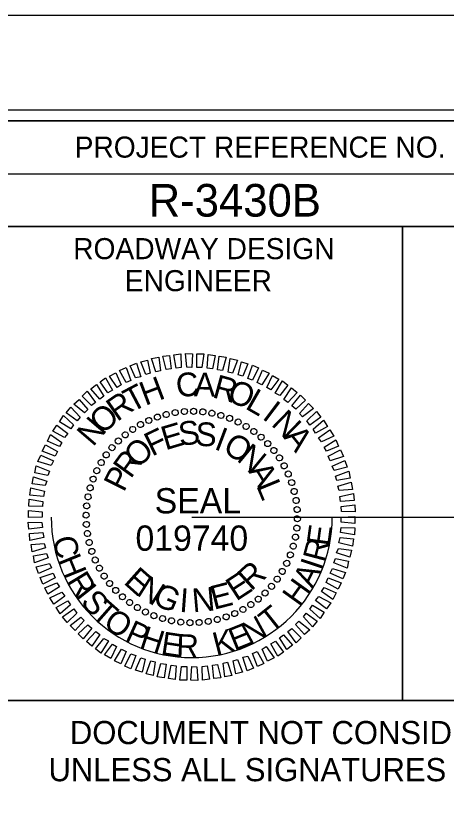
# Model space of a CAD drawing. Extents: x 1263639 to 1265460, y 747271 to 748371.
# Drawn here: x 1265113.9 to 1265216.1, y 748185.2 to 748370.7 of the extents above; entities that cross this region are included whole.
import ezdxf

# ---------------------------------------------------------------- set-up
doc = ezdxf.new("R2010")
doc.units = 0
for name, color, linetype in [('Prop Drainage Structure Bridge', 7, 'Continuous'), ('Prop Drainage Structure Bridge Opening', 7, 'Continuous'), ('Prop Grid Mask', 7, 'Continuous'), ('Prop Horizontal Alignment', 7, 'Continuous'), ('Prop Paved Shoulder', 7, 'Continuous'), ('Prop Terminator CELL', 7, 'Continuous'), ('Prop VPI Label', 7, 'Continuous'), ('Sheet Border Standard 30in CELL', 7, 'Continuous'), ('Sheet Layout Plan Border', 7, 'Continuous')]:
    doc.layers.add(name, color=color, linetype=linetype)

msp = doc.modelspace()

# ---------------------------------------------------------------- linework, layer by layer
at = {"layer": 'Prop Drainage Structure Bridge'}
for p, q in [((1265151.8, 748276.5), (1265151.8, 748276.5)), ((1265153.95, 748276.8), (1265153.95, 748276.8)), ((1265156.15, 748276.85), (1265156.15, 748276.85)), ((1265158.35, 748276.7), (1265158.35, 748276.7)), ((1265160.5, 748276.35), (1265160.5, 748276.35)), ((1265145.5, 748274.7), (1265145.5, 748274.7)), ((1265147.5, 748275.5), (1265147.5, 748275.5)), ((1265149.6, 748276.1), (1265149.6, 748276.1)), ((1265162.6, 748275.9), (1265162.6, 748275.9)), ((1265164.7, 748275.2), (1265164.7, 748275.2)), ((1265166.7, 748274.3), (1265166.7, 748274.3)), ((1265141.65, 748272.55), (1265141.65, 748272.55)), ((1265143.55, 748273.7), (1265143.55, 748273.7)), ((1265168.65, 748273.3), (1265168.65, 748273.3)), ((1265139.9, 748271.3), (1265139.9, 748271.3)), ((1265170.45, 748272.05), (1265170.45, 748272.05)), ((1265172.2, 748270.7), (1265172.2, 748270.7)), ((1265138.25, 748269.8), (1265138.25, 748269.8)), ((1265173.75, 748269.2), (1265173.75, 748269.2)), ((1265136.75, 748268.25), (1265136.75, 748268.25)), ((1265175.25, 748267.55), (1265175.25, 748267.55)), ((1265135.4, 748266.5), (1265135.4, 748266.5)), ((1265176.5, 748265.8), (1265176.5, 748265.8)), ((1265134.15, 748264.7), (1265134.15, 748264.7)), ((1265177.65, 748263.9), (1265177.65, 748263.9)), ((1265133.15, 748262.75), (1265133.15, 748262.75)), ((1265178.65, 748261.95), (1265178.65, 748261.95)), ((1265132.25, 748260.75), (1265132.25, 748260.75)), ((1265179.45, 748259.95), (1265179.45, 748259.95)), ((1265131.55, 748258.65), (1265131.55, 748258.65)), ((1265180.05, 748257.85), (1265180.05, 748257.85)), ((1265131.1, 748256.55), (1265131.1, 748256.55)), ((1265130.75, 748254.4), (1265130.75, 748254.4)), ((1265180.45, 748255.65), (1265180.45, 748255.65)), ((1265130.6, 748252.2), (1265130.6, 748252.2)), ((1265180.75, 748253.5), (1265180.75, 748253.5)), ((1265155.7, 748251.75), (1265155.7, 748251.75)), ((1265180.8, 748251.3), (1265180.8, 748251.3)), ((1265130.65, 748250), (1265130.65, 748250)), ((1265180.65, 748249.1), (1265180.65, 748249.1)), ((1265130.95, 748247.85), (1265130.95, 748247.85)), ((1265180.3, 748246.95), (1265180.3, 748246.95)), ((1265131.35, 748245.65), (1265131.35, 748245.65)), ((1265179.85, 748244.85), (1265179.85, 748244.85)), ((1265131.95, 748243.55), (1265131.95, 748243.55)), ((1265179.15, 748242.75), (1265179.15, 748242.75)), ((1265132.75, 748241.55), (1265132.75, 748241.55)), ((1265133.75, 748239.6), (1265133.75, 748239.6)), ((1265178.25, 748240.75), (1265178.25, 748240.75)), ((1265134.9, 748237.7), (1265134.9, 748237.7)), ((1265177.25, 748238.8), (1265177.25, 748238.8)), ((1265136.15, 748235.95), (1265136.15, 748235.95)), ((1265176, 748237), (1265176, 748237)), ((1265137.65, 748234.3), (1265137.65, 748234.3)), ((1265173.15, 748233.7), (1265173.15, 748233.7)), ((1265174.65, 748235.25), (1265174.65, 748235.25)), ((1265139.2, 748232.8), (1265139.2, 748232.8)), ((1265171.5, 748232.2), (1265171.5, 748232.2)), ((1265140.95, 748231.45), (1265140.95, 748231.45)), ((1265142.75, 748230.2), (1265142.75, 748230.2)), ((1265167.85, 748229.8), (1265167.85, 748229.8)), ((1265169.75, 748230.95), (1265169.75, 748230.95)), ((1265144.7, 748229.2), (1265144.7, 748229.2)), ((1265146.7, 748228.3), (1265146.7, 748228.3)), ((1265163.9, 748228), (1265163.9, 748228)), ((1265165.9, 748228.8), (1265165.9, 748228.8)), ((1265148.8, 748227.6), (1265148.8, 748227.6)), ((1265150.9, 748227.15), (1265150.9, 748227.15)), ((1265153.05, 748226.8), (1265153.05, 748226.8)), ((1265155.25, 748226.65), (1265155.25, 748226.65)), ((1265157.45, 748226.7), (1265157.45, 748226.7)), ((1265159.6, 748227), (1265159.6, 748227)), ((1265161.8, 748227.4), (1265161.8, 748227.4))]:
    msp.add_line(p, q, dxfattribs=at)
for points in [[(1265147.2, 748286.2), (1265146.15, 748289.35), (1265147.85, 748289.7), (1265148.25, 748286.45)], [(1265149.6, 748286.75), (1265148.8, 748289.95), (1265150.45, 748290.1), (1265150.8, 748286.9)], [(1265152, 748287.05), (1265151.45, 748290.25), (1265153.15, 748290.45), (1265153.2, 748287.2)], [(1265154.5, 748287.3), (1265154.25, 748290.55), (1265155.9, 748290.5), (1265155.7, 748287.25)], [(1265156.9, 748287.25), (1265156.9, 748290.5), (1265158.55, 748290.45), (1265158.1, 748287.2)], [(1265159.4, 748287.1), (1265159.6, 748290.35), (1265161.25, 748290.05), (1265160.6, 748286.9)], [(1265161.8, 748286.7), (1265162.25, 748289.9), (1265163.9, 748289.65), (1265163, 748286.55)], [(1265164.35, 748286.15), (1265164.85, 748289.4), (1265166.55, 748289), (1265165.4, 748285.9)], [(1265142.35, 748284.75), (1265141.05, 748287.65), (1265142.55, 748288.25), (1265143.6, 748285.05)], [(1265144.8, 748285.55), (1265143.65, 748288.55), (1265145.2, 748289), (1265145.85, 748285.9)], [(1265166.75, 748285.5), (1265167.5, 748288.6), (1265169.05, 748288.1), (1265167.8, 748285.15)], [(1265169, 748284.6), (1265170.15, 748287.75), (1265171.55, 748287.15), (1265170.15, 748284.25)], [(1265138, 748282.5), (1265136.15, 748285.2), (1265137.7, 748286), (1265138.95, 748283.1)], [(1265140.15, 748283.7), (1265138.55, 748286.5), (1265140.1, 748287.2), (1265141.25, 748284.15)], [(1265171.25, 748283.65), (1265172.5, 748286.6), (1265174.05, 748285.9), (1265172.35, 748283.1)], [(1265135.8, 748281.25), (1265133.95, 748283.8), (1265135.25, 748284.75), (1265136.9, 748281.85)], [(1265173.55, 748282.5), (1265174.9, 748285.35), (1265176.4, 748284.5), (1265174.5, 748281.9)], [(1265175.5, 748281.15), (1265177.25, 748284.05), (1265178.55, 748283), (1265176.6, 748280.55)], [(1265133.9, 748279.75), (1265131.75, 748282.15), (1265133.1, 748283.2), (1265134.85, 748280.4)], [(1265177.55, 748279.65), (1265179.4, 748282.4), (1265180.7, 748281.3), (1265178.5, 748278.95)], [(1265131.9, 748278.2), (1265129.7, 748280.4), (1265130.9, 748281.6), (1265132.85, 748278.9)], [(1265179.45, 748278.1), (1265181.5, 748280.7), (1265182.7, 748279.5), (1265180.4, 748277.35)], [(1265130.25, 748276.45), (1265127.7, 748278.5), (1265128.95, 748279.65), (1265131.05, 748277.25)], [(1265181.25, 748276.35), (1265183.4, 748278.7), (1265184.6, 748277.5), (1265182, 748275.55)], [(1265128.5, 748274.55), (1265125.9, 748276.5), (1265127, 748277.8), (1265129.2, 748275.45)], [(1265183, 748274.55), (1265185.3, 748276.8), (1265186.35, 748275.45), (1265183.7, 748273.55)], [(1265127, 748272.65), (1265124.3, 748274.35), (1265125.25, 748275.8), (1265127.65, 748273.6)], [(1265184.5, 748272.6), (1265186.95, 748274.7), (1265187.9, 748273.25), (1265185.1, 748271.65)], [(1265125.5, 748270.65), (1265122.7, 748272.15), (1265123.7, 748273.55), (1265126.3, 748271.55)], [(1265185.8, 748270.55), (1265188.45, 748272.45), (1265189.4, 748270.95), (1265186.5, 748269.55)], [(1265124.3, 748268.5), (1265121.45, 748269.75), (1265122.2, 748271.3), (1265124.9, 748269.45)], [(1265123.3, 748266.2), (1265120.2, 748267.35), (1265120.95, 748268.9), (1265123.8, 748267.3)], [(1265187.1, 748268.35), (1265189.9, 748270.1), (1265190.55, 748268.55), (1265187.7, 748267.4)], [(1265188.1, 748266.2), (1265191.05, 748267.7), (1265191.7, 748266.1), (1265188.6, 748265.1)], [(1265122.3, 748264), (1265119.2, 748264.9), (1265119.85, 748266.45), (1265122.85, 748265.05)], [(1265189, 748263.85), (1265192.05, 748265.15), (1265192.6, 748263.6), (1265189.5, 748262.8)], [(1265121.55, 748261.6), (1265118.45, 748262.25), (1265118.8, 748263.9), (1265121.95, 748262.65)], [(1265120.9, 748259.2), (1265117.8, 748259.6), (1265118.15, 748261.3), (1265121.3, 748260.25)], [(1265189.8, 748261.45), (1265193, 748262.6), (1265193.3, 748260.95), (1265190.15, 748260.4)], [(1265190.4, 748259.05), (1265193.55, 748260), (1265193.85, 748258.3), (1265190.7, 748258)], [(1265120.5, 748256.65), (1265117.3, 748256.95), (1265117.5, 748258.65), (1265120.75, 748257.85)], [(1265120.25, 748254.25), (1265117, 748254.35), (1265117.1, 748256), (1265120.35, 748255.45)], [(1265190.85, 748256.65), (1265194.1, 748257.35), (1265194.25, 748255.65), (1265191.05, 748255.45)], [(1265191.15, 748254.25), (1265194.4, 748254.65), (1265194.5, 748252.95), (1265191.25, 748253.05)], [(1265120.2, 748251.75), (1265116.95, 748251.6), (1265116.95, 748253.3), (1265120.2, 748252.95)], [(1265120.25, 748249.25), (1265117, 748248.85), (1265116.9, 748250.55), (1265120.15, 748250.45)], [(1265191.2, 748251.75), (1265194.45, 748251.9), (1265194.45, 748250.2), (1265191.2, 748250.55)], [(1265191.15, 748249.25), (1265194.4, 748249.15), (1265194.3, 748247.5), (1265191.05, 748248.05)], [(1265120.55, 748246.85), (1265117.3, 748246.15), (1265117.15, 748247.85), (1265120.35, 748248.05)], [(1265190.9, 748246.85), (1265194.1, 748246.55), (1265193.9, 748244.85), (1265190.65, 748245.65)], [(1265121, 748244.45), (1265117.85, 748243.5), (1265117.55, 748245.2), (1265120.7, 748245.5)], [(1265121.6, 748242.05), (1265118.4, 748240.9), (1265118.1, 748242.55), (1265121.25, 748243.1)], [(1265190.5, 748244.3), (1265193.6, 748243.9), (1265193.25, 748242.2), (1265190.1, 748243.25)], [(1265189.85, 748241.9), (1265192.95, 748241.25), (1265192.6, 748239.6), (1265189.45, 748240.85)], [(1265122.4, 748239.65), (1265119.35, 748238.35), (1265118.8, 748239.9), (1265121.9, 748240.7)], [(1265189.1, 748239.5), (1265192.2, 748238.6), (1265191.55, 748237.05), (1265188.55, 748238.45)], [(1265123.3, 748237.3), (1265120.35, 748235.8), (1265119.7, 748237.4), (1265122.8, 748238.4)], [(1265188.1, 748237.3), (1265191.2, 748236.15), (1265190.45, 748234.6), (1265187.6, 748236.2)], [(1265124.3, 748235.15), (1265121.5, 748233.4), (1265120.85, 748234.95), (1265123.7, 748236.1)], [(1265125.6, 748232.95), (1265122.95, 748231.05), (1265122, 748232.55), (1265124.9, 748233.95)], [(1265187.1, 748235), (1265189.95, 748233.75), (1265189.2, 748232.2), (1265186.5, 748234.05)], [(1265126.9, 748230.9), (1265124.45, 748228.8), (1265123.5, 748230.25), (1265126.3, 748231.85)], [(1265185.9, 748232.85), (1265188.7, 748231.35), (1265187.7, 748229.95), (1265185.1, 748231.95)], [(1265128.4, 748228.95), (1265126.1, 748226.7), (1265125.05, 748228.05), (1265127.7, 748229.95)], [(1265184.4, 748230.85), (1265187.1, 748229.15), (1265186.15, 748227.7), (1265183.75, 748229.9)], [(1265130.15, 748227.15), (1265128, 748224.8), (1265126.8, 748226), (1265129.4, 748227.95)], [(1265182.9, 748228.95), (1265185.5, 748227), (1265184.4, 748225.7), (1265182.2, 748228.05)], [(1265131.95, 748225.4), (1265129.9, 748222.8), (1265128.7, 748224), (1265131, 748226.15)], [(1265181.15, 748227.05), (1265183.7, 748225), (1265182.45, 748223.85), (1265180.35, 748226.25)], [(1265133.85, 748223.85), (1265132, 748221.1), (1265130.7, 748222.2), (1265132.9, 748224.55)], [(1265179.5, 748225.3), (1265181.7, 748223.1), (1265180.5, 748221.9), (1265178.55, 748224.6)], [(1265135.9, 748222.35), (1265134.15, 748219.45), (1265132.85, 748220.5), (1265134.8, 748222.95)], [(1265177.5, 748223.75), (1265179.65, 748221.35), (1265178.3, 748220.3), (1265176.55, 748223.1)], [(1265137.85, 748221), (1265136.5, 748218.15), (1265135, 748219), (1265136.9, 748221.6)], [(1265173.4, 748221), (1265175.25, 748218.3), (1265173.7, 748217.5), (1265172.45, 748220.4)], [(1265175.6, 748222.25), (1265177.45, 748219.7), (1265176.15, 748218.75), (1265174.5, 748221.65)], [(1265140.15, 748219.85), (1265138.9, 748216.9), (1265137.35, 748217.6), (1265139.05, 748220.4)], [(1265142.4, 748218.9), (1265141.25, 748215.75), (1265139.85, 748216.35), (1265141.25, 748219.25)], [(1265169.05, 748218.75), (1265170.35, 748215.85), (1265168.85, 748215.25), (1265167.8, 748218.45)], [(1265171.25, 748219.8), (1265172.85, 748217), (1265171.3, 748216.3), (1265170.15, 748219.35)], [(1265144.65, 748218), (1265143.9, 748214.9), (1265142.35, 748215.4), (1265143.6, 748218.35)], [(1265147.05, 748217.35), (1265146.55, 748214.1), (1265144.85, 748214.5), (1265146, 748217.6)], [(1265149.6, 748216.8), (1265149.15, 748213.6), (1265147.5, 748213.85), (1265148.4, 748216.95)], [(1265164.2, 748217.3), (1265165.25, 748214.15), (1265163.55, 748213.8), (1265163.15, 748217.05)], [(1265166.6, 748217.95), (1265167.75, 748214.95), (1265166.2, 748214.5), (1265165.55, 748217.6)], [(1265152, 748216.4), (1265151.8, 748213.15), (1265150.15, 748213.45), (1265150.8, 748216.6)], [(1265154.5, 748216.25), (1265154.5, 748213), (1265152.85, 748213.05), (1265153.3, 748216.3)], [(1265156.9, 748216.2), (1265157.15, 748212.95), (1265155.5, 748213), (1265155.7, 748216.25)], [(1265159.4, 748216.45), (1265159.95, 748213.25), (1265158.25, 748213.05), (1265158.2, 748216.3)], [(1265161.8, 748216.75), (1265162.6, 748213.55), (1265160.95, 748213.4), (1265160.6, 748216.6)]]:
    msp.add_lwpolyline(points, close=True, dxfattribs=at)
for centre, major_axis in [((1265147.54, 748275.47), (-0.234, 0.681)), ((1265149.64, 748276.09), (-0.174, 0.699)), ((1265151.78, 748276.52), (-0.113, 0.711)), ((1265153.95, 748276.77), (-0.05, 0.718)), ((1265156.14, 748276.83), (0.013, 0.72)), ((1265158.32, 748276.7), (0.075, 0.716)), ((1265160.49, 748276.37), (0.137, 0.707)), ((1265162.62, 748275.86), (0.198, 0.692)), ((1265143.54, 748273.69), (-0.349, 0.63)), ((1265145.5, 748274.66), (-0.293, 0.658)), ((1265164.69, 748275.17), (0.258, 0.672)), ((1265166.7, 748274.29), (0.316, 0.647)), ((1265141.68, 748272.55), (-0.403, 0.597)), ((1265168.62, 748273.25), (0.371, 0.617)), ((1265170.44, 748272.04), (0.423, 0.582)), ((1265138.28, 748269.79), (-0.5, 0.518)), ((1265139.92, 748271.24), (-0.453, 0.56)), ((1265172.16, 748270.68), (0.472, 0.543)), ((1265136.77, 748268.21), (-0.543, 0.472)), ((1265173.74, 748269.17), (0.518, 0.5)), ((1265135.41, 748266.49), (-0.582, 0.423)), ((1265175.19, 748267.54), (0.56, 0.453)), ((1265134.21, 748264.67), (-0.617, 0.371)), ((1265176.5, 748265.78), (0.597, 0.403)), ((1265133.16, 748262.75), (-0.647, 0.316)), ((1265177.64, 748263.91), (0.63, 0.349)), ((1265132.29, 748260.74), (-0.672, 0.258)), ((1265178.61, 748261.95), (0.658, 0.293)), ((1265131.59, 748258.67), (-0.692, 0.198)), ((1265179.42, 748259.92), (0.681, 0.234)), ((1265180.04, 748257.82), (0.699, 0.174)), ((1265131.08, 748256.54), (-0.707, 0.137)), ((1265180.47, 748255.68), (0.711, 0.113)), ((1265130.76, 748254.37), (-0.716, 0.075)), ((1265180.72, 748253.5), (0.718, 0.05)), ((1265130.63, 748252.19), (-0.72, 0.013)), ((1265180.78, 748251.32), (0.72, -0.013)), ((1265130.68, 748250), (-0.718, -0.05)), ((1265130.93, 748247.83), (-0.711, -0.113)), ((1265180.65, 748249.13), (0.716, -0.075)), ((1265131.37, 748245.69), (-0.699, -0.174)), ((1265180.32, 748246.97), (0.707, -0.137)), ((1265179.81, 748244.84), (0.692, -0.198)), ((1265131.99, 748243.59), (-0.681, -0.234)), ((1265179.12, 748242.76), (0.672, -0.258)), ((1265132.79, 748241.55), (-0.658, -0.293)), ((1265178.24, 748240.76), (0.647, -0.316)), ((1265133.77, 748239.59), (-0.63, -0.349)), ((1265177.2, 748238.84), (0.617, -0.371)), ((1265134.91, 748237.73), (-0.597, -0.403)), ((1265175.99, 748237.01), (0.582, -0.423)), ((1265136.21, 748235.97), (-0.56, -0.453)), ((1265174.63, 748235.3), (0.543, -0.472)), ((1265137.66, 748234.33), (-0.518, -0.5)), ((1265139.25, 748232.82), (-0.472, -0.543)), ((1265173.12, 748233.71), (0.5, -0.518)), ((1265140.96, 748231.46), (-0.423, -0.582)), ((1265169.73, 748230.96), (0.403, -0.597)), ((1265171.49, 748232.26), (0.453, -0.56)), ((1265142.79, 748230.26), (-0.371, -0.617)), ((1265144.71, 748229.21), (-0.316, -0.647)), ((1265167.86, 748229.82), (0.349, -0.63)), ((1265146.71, 748228.34), (-0.258, -0.672)), ((1265148.79, 748227.64), (-0.198, -0.692)), ((1265150.92, 748227.13), (-0.137, -0.707)), ((1265161.77, 748227.42), (0.174, -0.699)), ((1265163.87, 748228.04), (0.234, -0.681)), ((1265165.9, 748228.84), (0.293, -0.658)), ((1265153.08, 748226.81), (-0.075, -0.716)), ((1265155.27, 748226.68), (-0.013, -0.72)), ((1265157.45, 748226.73), (0.05, -0.718)), ((1265159.63, 748226.98), (0.113, -0.711))]:
    msp.add_ellipse(centre, major_axis=major_axis, ratio=0.999708, dxfattribs=at)
at = {"layer": 'Prop Drainage Structure Bridge Opening'}
msp.add_line((1265322.75, 748370.74), (1263638.75, 748370.74), dxfattribs=at)
at = {"layer": 'Prop Grid Mask'}
for q in [(1265460.4, 748251.75), (1265155.7, 748251.75)]:
    msp.add_line((1265155.7, 748251.75), q, dxfattribs=at)
at = {"layer": 'Prop Horizontal Alignment'}
msp.add_arc((1265155.7, 748251.75), 33.36, 180, 360, dxfattribs=at)
at = {"layer": 'Prop Paved Shoulder'}
for p, q in [((1265105.7, 748333.19), (1265305.75, 748333.19)), ((1265205.75, 748320.69), (1265205.75, 748208.24))]:
    msp.add_line(p, q, dxfattribs=at)
for points in [[(1265305.75, 748345.74), (1263805.75, 748345.74), (1263805.75, 747295.74), (1265305.75, 747295.74)], [(1265105.7, 748345.74), (1265305.75, 748345.74), (1265305.75, 748320.69), (1265105.7, 748320.69)], [(1265105.7, 748320.69), (1265205.75, 748320.69), (1265205.75, 748208.19), (1265105.7, 748208.19)], [(1265205.75, 748320.69), (1265305.75, 748320.69), (1265305.75, 748208.19), (1265205.75, 748208.19)]]:
    msp.add_lwpolyline(points, close=True, dxfattribs=at)
at = {"layer": 'Prop Terminator CELL'}
msp.add_lwpolyline([(1265318.25, 748348.29), (1263651.75, 748348.29), (1263651.75, 747293.19), (1265318.25, 747293.19)], close=True, dxfattribs=at)
at = {"layer": 'Prop VPI Label'}
msp.add_lwpolyline([(1265322.75, 748370.74), (1263638.75, 748370.74), (1263638.75, 747270.74), (1265322.75, 747270.74)], close=True, dxfattribs=at)
at = {"layer": 'Sheet Layout Plan Border'}
msp.add_line((1265105.7, 748208.19), (1265305.74, 748208.19), dxfattribs=at)

# ---------------------------------------------------------------- texts
at = {"layer": 'Prop Drainage Structure Bridge'}
for s, height, rotation, p in [('C', 5.64, 6.2199, (1265152.25, 748280.1)), ('A', 5.64, 359.0203, (1265156.2, 748280.4)), ('R', 5.64, 344.6211, (1265160.4, 748280.2)), ('H', 5.64, 20.6195, (1265144.65, 748278.1)), ('O', 5.64, 337.4212, (1265163.75, 748279.45)), ('T', 5.64, 27.8198, (1265141.4, 748276.45)), ('L', 5.64, 330.2209, (1265168.15, 748277.6)), ('R', 5.64, 35.0205, (1265138, 748274.25)), ('O', 5.64, 42.2217, (1265134.55, 748271.15)), ('I', 5.64, 323.0201, (1265172.2, 748275.2)), ('N', 5.64, 315.8189, (1265174.35, 748273.65)), ('N', 5.64, 49.4235, (1265132.25, 748268.25)), ('S', 5.64, 7.2556, (1265152.9, 748268.6)), ('S', 5.64, 357.9004, (1265156.5, 748268.65)), ('F', 5.64, 25.967, (1265146.25, 748266.05)), ('E', 5.64, 16.6111, (1265149.45, 748267.55)), ('I', 5.64, 339.1896, (1265160.8, 748267.95)), ('A', 5.64, 308.6172, (1265177.3, 748270.7)), ('O', 5.64, 329.8335, (1265162.8, 748267.25)), ('O', 5.64, 44.6812, (1265142.95, 748263.1)), ('N', 5.64, 320.4766, (1265166.15, 748265.25)), ('R', 5.64, 54.0397, (1265141.2, 748260.65)), ('P', 5.64, 63.3989, (1265139.6, 748257.45)), ('A', 5.64, 301.7603, (1265169, 748262.65)), ('L', 5.64, 292.4008, (1265170.95, 748259.2)), ('SEAL', 5.998, 360, (1265146.9, 748252.6)), ('019740', 5.998, 360, (1265142.34, 748243.74)), ('E', 5.5, 82.1825, (1265188.41, 748244.66)), ('C', 5.5, 283.2464, (1265122.63, 748246.62)), ('R', 5.5, 75.2561, (1265187.31, 748240.76)), ('H', 5.5, 292.1191, (1265123.82, 748241.58)), ('I', 5.5, 71.7356, (1265186.58, 748238.84)), ('E', 5.64, 318.2769, (1265139.3, 748236.1)), ('R', 5.64, 42.4814, (1265169.8, 748234)), ('A', 5.5, 63.5498, (1265184.42, 748234.58)), ('R', 5.5, 301.3639, (1265125.87, 748236.59)), ('N', 5.64, 327.634, (1265142.3, 748233.4)), ('E', 5.64, 33.1241, (1265166.25, 748231.65)), ('H', 5.5, 54.305, (1265181.29, 748230.19)), ('I', 5.5, 308.2904, (1265127.92, 748233.11)), ('G', 5.64, 336.9902, (1265146.1, 748231.15)), ('E', 5.64, 14.4118, (1265160.95, 748229.7)), ('S', 5.5, 311.8108, (1265129.11, 748231.44)), ('I', 5.64, 355.7012, (1265152.65, 748229.25)), ('N', 5.64, 5.0564, (1265156, 748229.1)), ('T', 5.5, 318.5942, (1265131.7, 748228.44)), ('T', 5.5, 38.5631, (1265174.48, 748224.05)), ('O', 5.5, 324.8909, (1265134.4, 748225.94)), ('N', 5.5, 28.6314, (1265169.42, 748221.23)), ('P', 5.5, 335.5954, (1265139.57, 748222.44)), ('E', 5.5, 22.0484, (1265165.83, 748219.86)), ('H', 5.5, 342.1784, (1265143.03, 748220.78)), ('E', 5.5, 351.4232, (1265148.17, 748219.15)), ('K', 5.5, 14.3778, (1265161.49, 748218.79)), ('R', 5.5, 358.0062, (1265151.96, 748218.5))]:
    msp.add_text(s, height=height, rotation=rotation, dxfattribs=at).set_placement(p)
at = {"layer": 'Prop Paved Shoulder'}
for s, height, p in [('PROJECT REFERENCE NO.', 5.0001, (1265127.9, 748337.04)), ('ROADWAY DESIGN', 5.0001, (1265127.56, 748312.94)), ('ENGINEER', 5, (1265139.81, 748305.34))]:
    msp.add_text(s, height=height, dxfattribs=at).set_placement(p)
at = {"layer": 'Sheet Border Standard 30in CELL'}
msp.add_text('R-3430B', height=7.75, dxfattribs=at).set_placement((1265145.47, 748323.04))
at = {"layer": 'Sheet Layout Plan Border'}
for s, p in [('DOCUMENT NOT CONSIDERED FINAL', (1265126.78, 748197.84)), ('UNLESS ALL SIGNATURES COMPLETED', (1265121.7, 748189.04))]:
    msp.add_text(s, height=5.5, dxfattribs=at).set_placement(p)

doc.saveas('drawing.dxf')
